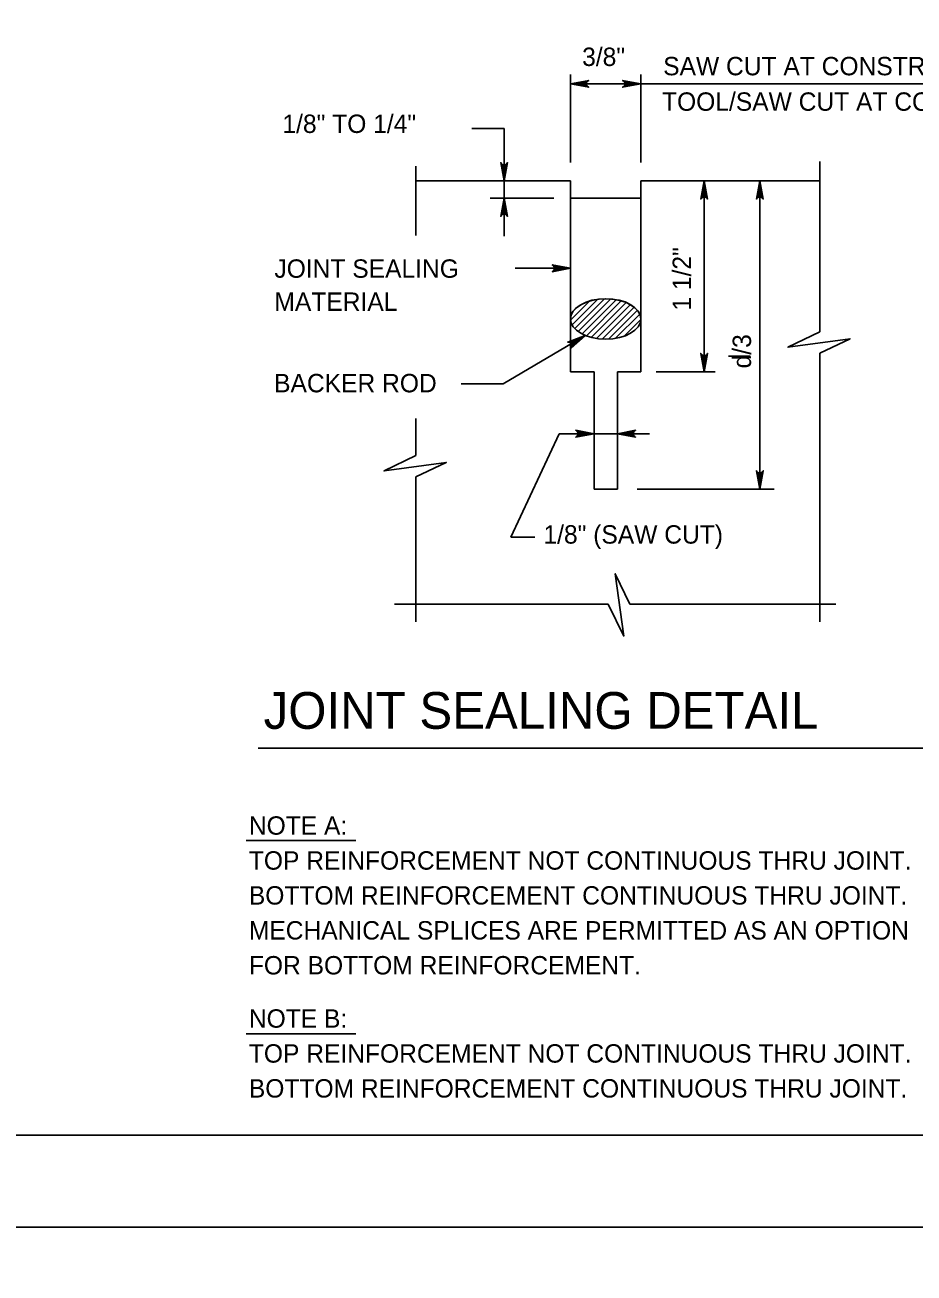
# Model space of a CAD drawing. Extents: x 638079 to 640019, y 297691 to 298879.
# Drawn here: x 638465.1 to 638610.1, y 298277.7 to 298481.4 of the extents above; entities that cross this region are included whole.
import ezdxf

# ---------------------------------------------------------------- set-up
doc = ezdxf.new("R2010")
doc.units = 0
for name, color, linetype in [('1', 7, 'Continuous'), ('Level 1', 7, 'Continuous'), ('PLT-BNDY', 7, 'Continuous')]:
    doc.layers.add(name, color=color, linetype=linetype)

msp = doc.modelspace()

# ---------------------------------------------------------------- linework, layer by layer
at = {"layer": '1'}
for p, q in [((638554.06, 298473.29), (638554.06, 298458.96)), ((638565.55, 298473.29), (638565.55, 298458.96)), ((638554.06, 298471.77), (638565.55, 298471.77)), ((638565.55, 298471.77), (638667.28, 298471.77)), ((638537.98, 298464.48), (638543.24, 298464.48)), ((638543.24, 298464.48), (638543.24, 298455.94)), ((638528.84, 298458.33), (638528.84, 298447.01)), ((638594.72, 298459.09), (638594.72, 298431.33)), ((638528.84, 298455.94), (638554.06, 298455.94)), ((638543.24, 298455.94), (638543.24, 298453.13)), ((638554.06, 298455.94), (638554.06, 298424.79)), ((638565.55, 298455.94), (638565.55, 298424.79)), ((638565.55, 298455.94), (638594.72, 298455.94)), ((638575.88, 298455.94), (638575.88, 298424.79)), ((638584.95, 298455.94), (638584.95, 298405.65)), ((638540.96, 298453.13), (638551.36, 298453.13)), ((638543.24, 298453.13), (638543.24, 298446.93)), ((638554.06, 298453.13), (638565.55, 298453.13)), ((638545.02, 298441.68), (638554.06, 298441.68)), ((638554.07, 298433.22), (638557.17, 298436.32)), ((638554.32, 298432.43), (638558.48, 298436.6)), ((638554.75, 298431.84), (638559.6, 298436.69)), ((638555.31, 298431.36), (638560.61, 298436.66)), ((638555.95, 298430.97), (638561.52, 298436.54)), ((638556.66, 298430.65), (638562.36, 298436.35)), ((638557.45, 298430.4), (638563.13, 298436.08)), ((638554.57, 298434.75), (638555.12, 298435.3)), ((638558.31, 298430.23), (638563.83, 298435.75)), ((638559.24, 298430.13), (638564.45, 298435.34)), ((638560.27, 298430.12), (638564.98, 298434.83)), ((638561.42, 298430.25), (638565.38, 298434.2)), ((638562.8, 298430.6), (638565.55, 298433.34)), ((638556.46, 298430.71), (638543.11, 298422.83)), ((638594.72, 298427.81), (638594.72, 298384)), ((638583.4, 298427.32), (638579.85, 298427.32)), ((638554.06, 298424.79), (638557.91, 298424.79)), ((638557.91, 298424.79), (638557.91, 298405.65)), ((638561.71, 298424.79), (638561.71, 298405.65)), ((638561.71, 298424.79), (638565.55, 298424.79)), ((638568.03, 298424.79), (638577.66, 298424.79)), ((638536.21, 298422.83), (638543.11, 298422.83)), ((638528.84, 298417.18), (638528.84, 298411.15)), ((638544.32, 298397.82), (638552.24, 298414.69)), ((638552.24, 298414.69), (638557.91, 298414.69)), ((638557.91, 298414.69), (638561.71, 298414.69)), ((638561.71, 298414.69), (638566.95, 298414.69)), ((638528.84, 298407.64), (638528.84, 298384)), ((638557.91, 298405.65), (638561.71, 298405.65)), ((638564.92, 298405.65), (638587.29, 298405.65)), ((638544.32, 298397.82), (638548.25, 298397.82)), ((638525.37, 298386.85), (638560.21, 298386.85)), ((638563.73, 298386.85), (638597.37, 298386.85)), ((638501.18, 298348.33), (638519.04, 298348.33)), ((638501.18, 298316.77), (638519.04, 298316.77))]:
    msp.add_line(p, q, dxfattribs=at)
for points in [[(639099.03, 298300.23), (639099.03, 298864.23), (638313.03, 298864.23), (638313.03, 298300.23), (639099.03, 298300.23), (639099.03, 298326.59), (638899.03, 298326.59), (638899.03, 298391.26), (639099.03, 298391.26), (639099.03, 298420.23), (638899.03, 298420.23), (638899.03, 298300.23), (638977.83, 298300.23), (638977.83, 298326.59), (638977.83, 298300.23), (639054.83, 298300.23), (639054.83, 298326.59), (639054.83, 298314.27), (639099.03, 298314.27)], [(638554.06, 298471.77), (638557.05, 298472.33), (638556.93, 298472.25), (638556.82, 298472.17), (638556.76, 298472.07), (638556.7, 298471.97), (638556.68, 298471.87), (638556.66, 298471.77), (638556.68, 298471.67), (638556.7, 298471.57), (638556.76, 298471.47), (638556.82, 298471.37), (638556.93, 298471.29), (638557.05, 298471.21), (638554.06, 298471.77), (638556.93, 298471.29), (638556.82, 298471.37), (638554.06, 298471.77), (638556.76, 298471.47), (638556.7, 298471.57), (638554.06, 298471.77), (638556.68, 298471.67), (638556.66, 298471.77), (638554.06, 298471.77), (638556.68, 298471.87), (638556.7, 298471.97), (638554.06, 298471.77), (638556.76, 298472.07), (638556.82, 298472.17), (638554.06, 298471.77), (638556.93, 298472.25)], [(638565.55, 298471.77), (638562.57, 298471.21), (638562.68, 298471.29), (638562.8, 298471.37), (638562.86, 298471.47), (638562.92, 298471.57), (638562.94, 298471.67), (638562.95, 298471.77), (638562.94, 298471.87), (638562.92, 298471.97), (638562.86, 298472.07), (638562.8, 298472.17), (638562.68, 298472.25), (638562.57, 298472.33), (638565.55, 298471.77), (638562.68, 298472.25), (638562.8, 298472.17), (638565.55, 298471.77), (638562.86, 298472.07), (638562.92, 298471.97), (638565.55, 298471.77), (638562.94, 298471.87), (638562.95, 298471.77), (638565.55, 298471.77), (638562.94, 298471.67), (638562.92, 298471.57), (638565.55, 298471.77), (638562.86, 298471.47), (638562.8, 298471.37), (638565.55, 298471.77), (638562.68, 298471.29)], [(638543.24, 298455.94), (638542.68, 298458.92), (638542.76, 298458.81), (638542.84, 298458.69), (638542.94, 298458.63), (638543.04, 298458.57), (638543.14, 298458.56), (638543.24, 298458.54), (638543.34, 298458.56), (638543.44, 298458.57), (638543.54, 298458.63), (638543.64, 298458.69), (638543.72, 298458.81), (638543.8, 298458.92), (638543.24, 298455.94), (638543.72, 298458.81), (638543.64, 298458.69), (638543.24, 298455.94), (638543.54, 298458.63), (638543.44, 298458.57), (638543.24, 298455.94), (638543.34, 298458.56), (638543.24, 298458.54), (638543.24, 298455.94), (638543.14, 298458.56), (638543.04, 298458.57), (638543.24, 298455.94), (638542.94, 298458.63), (638542.84, 298458.69), (638543.24, 298455.94), (638542.76, 298458.81)], [(638575.88, 298455.94), (638575.33, 298452.96), (638575.41, 298453.07), (638575.48, 298453.19), (638575.58, 298453.25), (638575.68, 298453.3), (638575.78, 298453.32), (638575.88, 298453.34), (638575.98, 298453.32), (638576.08, 298453.3), (638576.18, 298453.25), (638576.28, 298453.19), (638576.36, 298453.07), (638576.44, 298452.96), (638575.88, 298455.94), (638576.36, 298453.07), (638576.28, 298453.19), (638575.88, 298455.94), (638576.18, 298453.25), (638576.08, 298453.3), (638575.88, 298455.94), (638575.98, 298453.32), (638575.88, 298453.34), (638575.88, 298455.94), (638575.78, 298453.32), (638575.68, 298453.3), (638575.88, 298455.94), (638575.58, 298453.25), (638575.48, 298453.19), (638575.88, 298455.94), (638575.41, 298453.07)], [(638584.95, 298455.94), (638584.39, 298452.96), (638584.47, 298453.07), (638584.55, 298453.19), (638584.65, 298453.25), (638584.75, 298453.3), (638584.85, 298453.32), (638584.95, 298453.34), (638585.05, 298453.32), (638585.15, 298453.3), (638585.25, 298453.25), (638585.35, 298453.19), (638585.43, 298453.07), (638585.51, 298452.96), (638584.95, 298455.94), (638585.43, 298453.07), (638585.35, 298453.19), (638584.95, 298455.94), (638585.25, 298453.25), (638585.15, 298453.3), (638584.95, 298455.94), (638585.05, 298453.32), (638584.95, 298453.34), (638584.95, 298455.94), (638584.85, 298453.32), (638584.75, 298453.3), (638584.95, 298455.94), (638584.65, 298453.25), (638584.55, 298453.19), (638584.95, 298455.94), (638584.47, 298453.07)], [(638543.24, 298453.13), (638543.8, 298450.15), (638543.72, 298450.26), (638543.64, 298450.38), (638543.54, 298450.44), (638543.44, 298450.49), (638543.34, 298450.51), (638543.24, 298450.53), (638543.14, 298450.51), (638543.04, 298450.49), (638542.94, 298450.44), (638542.84, 298450.38), (638542.76, 298450.26), (638542.68, 298450.15), (638543.24, 298453.13), (638542.76, 298450.26), (638542.84, 298450.38), (638543.24, 298453.13), (638542.94, 298450.44), (638543.04, 298450.49), (638543.24, 298453.13), (638543.14, 298450.51), (638543.24, 298450.53), (638543.24, 298453.13), (638543.34, 298450.51), (638543.44, 298450.49), (638543.24, 298453.13), (638543.54, 298450.44), (638543.64, 298450.38), (638543.24, 298453.13), (638543.72, 298450.26)], [(638554.06, 298441.68), (638551.08, 298441.12), (638551.2, 298441.2), (638551.31, 298441.28), (638551.37, 298441.38), (638551.43, 298441.48), (638551.45, 298441.58), (638551.46, 298441.68), (638551.45, 298441.78), (638551.43, 298441.88), (638551.37, 298441.98), (638551.31, 298442.08), (638551.2, 298442.16), (638551.08, 298442.24), (638554.06, 298441.68), (638551.2, 298442.16), (638551.31, 298442.08), (638554.06, 298441.68), (638551.37, 298441.98), (638551.43, 298441.88), (638554.06, 298441.68), (638551.45, 298441.78), (638551.46, 298441.68), (638554.06, 298441.68), (638551.45, 298441.58), (638551.43, 298441.48), (638554.06, 298441.68), (638551.37, 298441.38), (638551.31, 298441.28), (638554.06, 298441.68), (638551.2, 298441.2)], [(638556.46, 298430.71), (638554.2, 298428.68), (638554.26, 298428.81), (638554.31, 298428.94), (638554.31, 298429.05), (638554.31, 298429.17), (638554.27, 298429.26), (638554.24, 298429.36), (638554.17, 298429.43), (638554.1, 298429.51), (638554, 298429.56), (638553.9, 298429.62), (638553.76, 298429.63), (638553.62, 298429.64), (638556.46, 298430.71), (638553.76, 298429.63), (638553.9, 298429.62), (638556.46, 298430.71), (638554, 298429.56), (638554.1, 298429.51), (638556.46, 298430.71), (638554.17, 298429.43), (638554.24, 298429.36), (638556.46, 298430.71), (638554.27, 298429.26), (638554.31, 298429.17), (638556.46, 298430.71), (638554.31, 298429.05), (638554.31, 298428.94), (638556.46, 298430.71), (638554.26, 298428.81)], [(638594.72, 298431.33), (638589.54, 298428.79), (638599.69, 298430.17), (638594.72, 298427.81)], [(638575.88, 298424.79), (638575.33, 298427.78), (638575.41, 298427.66), (638575.48, 298427.55), (638575.58, 298427.49), (638575.68, 298427.43), (638575.78, 298427.41), (638575.88, 298427.39), (638575.98, 298427.41), (638576.08, 298427.43), (638576.18, 298427.49), (638576.28, 298427.55), (638576.36, 298427.66), (638576.44, 298427.78), (638575.88, 298424.79), (638576.36, 298427.66), (638576.28, 298427.55), (638575.88, 298424.79), (638576.18, 298427.49), (638576.08, 298427.43), (638575.88, 298424.79), (638575.98, 298427.41), (638575.88, 298427.39), (638575.88, 298424.79), (638575.78, 298427.41), (638575.68, 298427.43), (638575.88, 298424.79), (638575.58, 298427.49), (638575.48, 298427.55), (638575.88, 298424.79), (638575.41, 298427.66)], [(638557.91, 298414.69), (638554.93, 298414.13), (638555.04, 298414.21), (638555.16, 298414.29), (638555.21, 298414.39), (638555.27, 298414.49), (638555.29, 298414.59), (638555.31, 298414.69), (638555.29, 298414.79), (638555.27, 298414.89), (638555.21, 298414.99), (638555.16, 298415.09), (638555.04, 298415.17), (638554.93, 298415.25), (638557.91, 298414.69), (638555.04, 298415.17), (638555.16, 298415.09), (638557.91, 298414.69), (638555.21, 298414.99), (638555.27, 298414.89), (638557.91, 298414.69), (638555.29, 298414.79), (638555.31, 298414.69), (638557.91, 298414.69), (638555.29, 298414.59), (638555.27, 298414.49), (638557.91, 298414.69), (638555.21, 298414.39), (638555.16, 298414.29), (638557.91, 298414.69), (638555.04, 298414.21)], [(638561.71, 298414.69), (638564.69, 298415.25), (638564.58, 298415.17), (638564.46, 298415.09), (638564.4, 298414.99), (638564.34, 298414.89), (638564.33, 298414.79), (638564.31, 298414.69), (638564.33, 298414.59), (638564.34, 298414.49), (638564.4, 298414.39), (638564.46, 298414.29), (638564.58, 298414.21), (638564.69, 298414.13), (638561.71, 298414.69), (638564.58, 298414.21), (638564.46, 298414.29), (638561.71, 298414.69), (638564.4, 298414.39), (638564.34, 298414.49), (638561.71, 298414.69), (638564.33, 298414.59), (638564.31, 298414.69), (638561.71, 298414.69), (638564.33, 298414.79), (638564.34, 298414.89), (638561.71, 298414.69), (638564.4, 298414.99), (638564.46, 298415.09), (638561.71, 298414.69), (638564.58, 298415.17)], [(638528.84, 298411.15), (638523.66, 298408.62), (638533.81, 298410), (638528.84, 298407.64)], [(638584.95, 298405.65), (638584.39, 298408.63), (638584.47, 298408.51), (638584.55, 298408.4), (638584.65, 298408.34), (638584.75, 298408.28), (638584.85, 298408.26), (638584.95, 298408.25), (638585.05, 298408.26), (638585.15, 298408.28), (638585.25, 298408.34), (638585.35, 298408.4), (638585.43, 298408.51), (638585.51, 298408.63), (638584.95, 298405.65), (638585.43, 298408.51), (638585.35, 298408.4), (638584.95, 298405.65), (638585.25, 298408.34), (638585.15, 298408.28), (638584.95, 298405.65), (638585.05, 298408.26), (638584.95, 298408.25), (638584.95, 298405.65), (638584.85, 298408.26), (638584.75, 298408.28), (638584.95, 298405.65), (638584.65, 298408.34), (638584.55, 298408.4), (638584.95, 298405.65), (638584.47, 298408.51)], [(638560.21, 298386.85), (638562.75, 298381.67), (638561.37, 298391.82), (638563.73, 298386.85)]]:
    msp.add_lwpolyline(points, dxfattribs=at)
msp.add_lwpolyline([(638554.06, 298453.13), (638554.06, 298433.4), (638554.15, 298434.06), (638554.44, 298434.6), (638554.9, 298435.11), (638555.64, 298435.68), (638556.77, 298436.2), (638557.56, 298436.45), (638558.73, 298436.66), (638559.7, 298436.69), (638560.78, 298436.64), (638562.01, 298436.45), (638562.99, 298436.18), (638563.93, 298435.71), (638564.53, 298435.28), (638565.07, 298434.76), (638565.47, 298434), (638565.55, 298433.4), (638565.55, 298453.13)], close=True, dxfattribs=at)
msp.add_ellipse((638559.81, 298433.4), major_axis=(5.74, 0), ratio=0.572391, dxfattribs=at)
at = {"layer": 'Level 1'}
msp.add_line((638503.1, 298363.39), (638623.14, 298363.39), dxfattribs=at)
at = {"layer": 'PLT-BNDY'}
for points in [[(638274.03, 298879.23), (639115.03, 298879.23), (639115.03, 298285.23), (638274.03, 298285.23)], [(638274.03, 298285.23), (639115.03, 298285.23), (639115.03, 297691.23), (638274.03, 297691.23)]]:
    msp.add_lwpolyline(points, close=True, dxfattribs=at)

# ---------------------------------------------------------------- texts
at = {"layer": '1'}
for s, height, p in [('3/8"', 3, (638555.97, 298474.69)), ('SAW CUT AT CONSTRUCTION JOINT', 3, (638569.19, 298473.17)), ('TOOL/SAW CUT AT CONTRACTION JOINT', 3, (638569, 298467.38)), ('1/8" TO 1/4"', 3, (638507.08, 298463.76)), ('JOINT SEALING', 3, (638505.77, 298440.13)), ('MATERIAL', 3, (638505.77, 298434.73)), ('BACKER ROD', 3, (638505.72, 298421.44)), ('1/8" (SAW CUT)', 3, (638549.66, 298396.75)), ('JOINT SEALING DETAIL', 6, (638504.01, 298366.53)), ('NOTE A:', 3, (638501.6, 298349.25)), ('TOP REINFORCEMENT NOT CONTINUOUS THRU JOINT.', 3, (638501.6, 298343.55)), ('BOTTOM REINFORCEMENT CONTINUOUS THRU JOINT.', 3, (638501.6, 298337.85)), ('MECHANICAL SPLICES ARE PERMITTED AS AN OPTION', 3, (638501.6, 298332.15)), ('FOR BOTTOM REINFORCEMENT.', 3, (638501.6, 298326.45)), ('NOTE B:', 3, (638501.6, 298317.76)), ('TOP REINFORCEMENT NOT CONTINUOUS THRU JOINT.', 3, (638501.6, 298312.06)), ('BOTTOM REINFORCEMENT CONTINUOUS THRU JOINT.', 3, (638501.6, 298306.36))]:
    msp.add_text(s, height=height, dxfattribs=at).set_placement(p)
for s, p in [('1 1/2"', (638573.73, 298434.77)), ('d/3', (638583.52, 298425.34))]:
    msp.add_text(s, height=3, rotation=90, dxfattribs=at).set_placement(p)

doc.saveas('drawing.dxf')
